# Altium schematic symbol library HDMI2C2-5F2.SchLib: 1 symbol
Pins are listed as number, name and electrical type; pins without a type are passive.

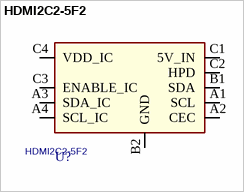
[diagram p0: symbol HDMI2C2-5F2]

## HDMI2C2-5F2
designator U?
footprint ST_CSP10N43x50P3x4_198x135x60
pins: A1 SCL, A2 CEC, A3 SDA_IC, A4 SCL_IC, B1 SDA, B2 GND, C1 5V_IN, C2 HPD, C3 ENABLE_IC, C4 VDD_IC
